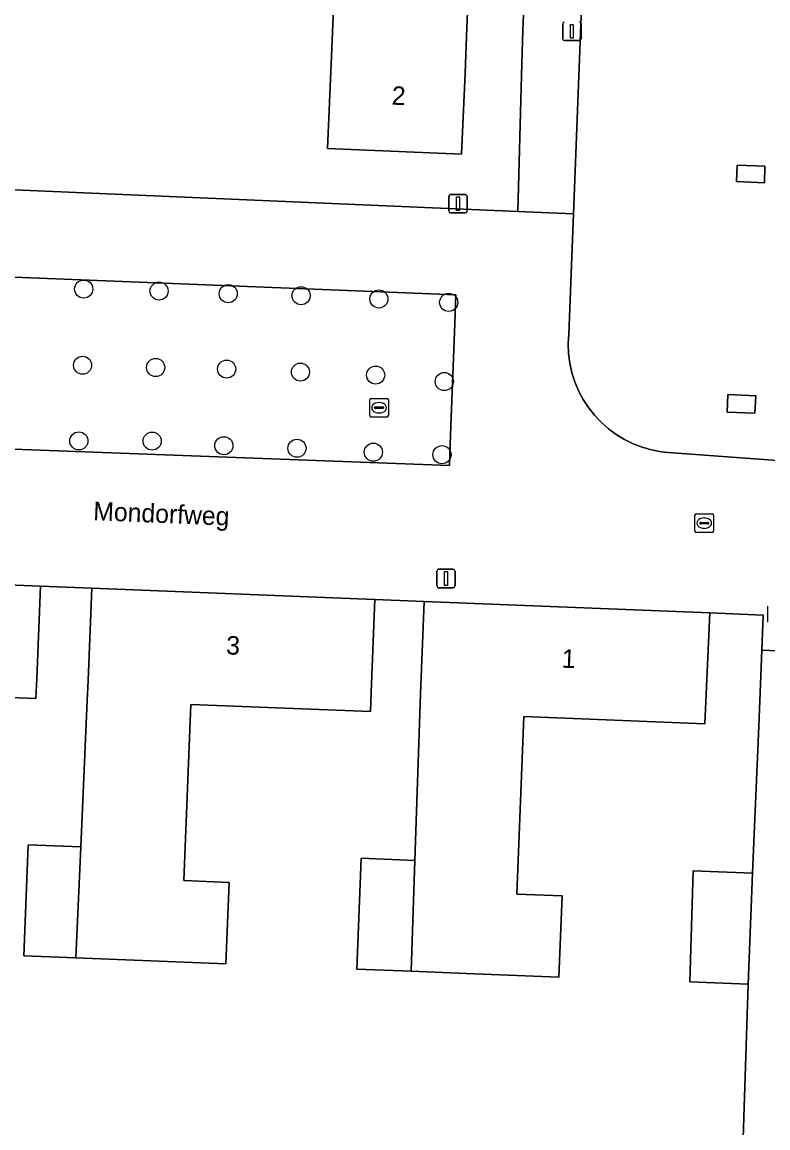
# Model space of a CAD drawing. Extents: x 160786 to 161429, y 386828 to 387485.
# Drawn here: x 160897.7 to 160938, y 387037.8 to 387097.5 of the extents above; entities that cross this region are included whole.
import ezdxf

# ---------------------------------------------------------------- set-up
doc = ezdxf.new("R2010")
doc.units = 0
for name, color, linetype in [('IMGEO_Boom', 7, 'Continuous'), ('IMGEO_Erf', 7, 'Continuous'), ('IMGEO_Kolk', 7, 'Continuous'), ('IMGEO_Lichtmast', 7, 'Continuous'), ('IMGEO_Muur', 7, 'Continuous'), ('IMGEO_Openbare_ruimte_label', 7, 'Continuous'), ('IMGEO_Pand', 7, 'Continuous'), ('IMGEO_Pand_nummerreeks', 7, 'Continuous'), ('IMGEO_Parkeervlak_open', 7, 'Continuous'), ('IMGEO_Rijbaan_lokaal_open', 7, 'Continuous'), ('IMGEO_Rioolput', 7, 'Continuous'), ('IMGEO_Voetpad_open', 7, 'Continuous')]:
    doc.layers.add(name, color=color, linetype=linetype)

msp = doc.modelspace()

# ---------------------------------------------------------------- linework, layer by layer
at = {"layer": 'IMGEO_Boom'}
for centre in [(160901.004, 387083.112), (160905.078, 387083), (160908.81, 387082.863), (160912.746, 387082.752), (160916.947, 387082.577), (160920.717, 387082.39), (160900.943, 387078.997), (160904.89, 387078.873), (160908.724, 387078.787), (160912.71, 387078.624), (160916.772, 387078.462), (160920.481, 387078.116), (160900.742, 387074.907), (160904.702, 387074.897), (160908.574, 387074.646), (160912.522, 387074.509), (160916.647, 387074.297), (160920.354, 387074.16)]:
    msp.add_circle(centre, 0.489, dxfattribs=at)
at = {"layer": 'IMGEO_Erf'}
for points in [[(160929.117, 387129.975), (160927.452, 387087.186), (160927.198, 387080.67), (160927.172, 387080.146), (160927.193, 387079.623), (160927.261, 387079.103), (160927.375, 387078.591), (160927.534, 387078.092), (160927.737, 387077.608), (160927.982, 387077.145), (160928.268, 387076.706), (160928.592, 387076.294), (160928.952, 387075.912), (160929.344, 387075.564), (160929.766, 387075.253), (160930.213, 387074.98), (160930.684, 387074.749), (160931.173, 387074.56), (160931.677, 387074.416), (160932.192, 387074.318), (160932.571, 387074.275), (160946.822, 387073.236)], [(160871.373, 387120.32), (160870.03, 387089.654), (160886.35, 387088.949), (160924.453, 387087.312), (160924.652, 387094.655), (160924.719, 387097.113), (160924.824, 387099.594)], [(160921.811, 387099.721), (160921.706, 387097.24), (160921.602, 387094.786), (160921.416, 387090.395), (160914.174, 387090.702), (160914.386, 387095.698), (160914.712, 387103.404)], [(160936.491, 387033.349), (160936.884, 387045.544), (160933.747, 387045.671), (160933.922, 387051.672), (160937.126, 387051.542), (160937.46, 387059.492), (160937.626, 387063.606), (160937.702, 387065.494), (160934.813, 387065.611), (160934.557, 387059.609), (160924.778, 387060.005), (160924.391, 387050.419), (160926.839, 387050.32), (160926.662, 387045.923), (160921.667, 387046.124), (160918.683, 387046.244), (160915.751, 387046.361), (160915.993, 387052.357), (160918.888, 387052.24), (160919.159, 387060.17), (160919.195, 387061.239), (160919.396, 387066.234), (160916.73, 387066.33), (160916.529, 387061.335), (160916.486, 387060.278), (160906.79, 387060.669), (160906.406, 387051.142), (160908.854, 387051.043), (160908.677, 387046.646), (160900.574, 387046.971), (160897.765, 387047.084), (160898.007, 387053.08), (160900.844, 387052.966), (160901.2, 387060.87), (160901.249, 387061.951), (160901.451, 387066.947), (160898.67, 387067.06), (160898.469, 387062.065), (160898.425, 387060.982), (160888.793, 387061.371)]]:
    msp.add_lwpolyline(points, dxfattribs=at)
for points in [[(160937.801, 387089.751), (160937.766, 387088.858), (160936.265, 387088.917), (160936.301, 387089.811)], [(160937.298, 387077.346), (160937.261, 387076.404), (160935.749, 387076.464), (160935.786, 387077.405)]]:
    msp.add_lwpolyline(points, close=True, dxfattribs=at)
at = {"layer": 'IMGEO_Kolk'}
for p, q in [((160916.458, 387076.271), (160916.458, 387077.123)), ((160916.533, 387077.197), (160917.385, 387077.197)), ((160916.76, 387076.74), (160917.158, 387076.74)), ((160916.946, 387076.977), (160916.971, 387076.977)), ((160917.459, 387077.123), (160917.459, 387076.271)), ((160917.385, 387076.197), (160916.533, 387076.197)), ((160916.717, 387076.691), (160916.717, 387076.703)), ((160917.155, 387076.654), (160916.757, 387076.654)), ((160916.969, 387076.417), (160916.944, 387076.417)), ((160917.201, 387076.703), (160917.201, 387076.691)), ((160934.017, 387070.035), (160934.017, 387070.887)), ((160934.092, 387070.961), (160934.944, 387070.961)), ((160935.018, 387070.887), (160935.018, 387070.035)), ((160934.276, 387070.455), (160934.276, 387070.467)), ((160934.714, 387070.418), (160934.316, 387070.418)), ((160934.319, 387070.504), (160934.717, 387070.504)), ((160934.528, 387070.181), (160934.503, 387070.181)), ((160934.505, 387070.741), (160934.53, 387070.741)), ((160934.76, 387070.467), (160934.76, 387070.455)), ((160934.944, 387069.961), (160934.092, 387069.961))]:
    msp.add_line(p, q, dxfattribs=at)
for points in [[(160916.458, 387076.271), (160916.458, 387077.123)], [(160916.533, 387077.197), (160917.385, 387077.197)], [(160917.459, 387077.123), (160917.459, 387076.271)], [(160917.385, 387076.197), (160916.533, 387076.197)], [(160934.017, 387070.035), (160934.017, 387070.887)], [(160934.092, 387070.961), (160934.944, 387070.961)], [(160935.018, 387070.887), (160935.018, 387070.035)], [(160934.944, 387069.961), (160934.092, 387069.961)]]:
    msp.add_lwpolyline(points, dxfattribs=at)
for centre, radius, start, end in [((160916.535, 387077.121), 0.0765, 91.55205, 178.44795), ((160916.535, 387077.121), 0.0765, 91.55205, 178.44795), ((160916.757, 387076.7), 0.0403, 85.87752, 175.75265), ((160917.162, 387076.702), 0.0386, 1.73085, 96.63898), ((160917.383, 387077.121), 0.0765, 1.55205, 88.44795), ((160917.383, 387077.121), 0.0765, 1.55205, 88.44795), ((160916.535, 387076.273), 0.0765, 181.55205, 268.44795), ((160916.535, 387076.273), 0.0765, 181.55205, 268.44795), ((160916.754, 387076.69), 0.0366, 178.93798, 274.71019), ((160917.158, 387076.697), 0.043, 264.86636, 352.45326), ((160917.383, 387076.273), 0.0765, 271.55205, 358.44795), ((160917.383, 387076.273), 0.0765, 271.55205, 358.44795), ((160934.094, 387070.885), 0.0765, 91.55205, 178.44795), ((160934.094, 387070.885), 0.0765, 91.55205, 178.44795), ((160934.942, 387070.885), 0.0765, 1.55205, 88.44795), ((160934.942, 387070.885), 0.0765, 1.55205, 88.44795), ((160934.316, 387070.464), 0.0403, 85.87752, 175.75265), ((160934.313, 387070.454), 0.0366, 178.93798, 274.71019), ((160934.717, 387070.461), 0.043, 264.86636, 352.45326), ((160934.721, 387070.466), 0.0386, 1.73085, 96.63898), ((160934.094, 387070.037), 0.0765, 181.55205, 268.44795), ((160934.094, 387070.037), 0.0765, 181.55205, 268.44795), ((160934.942, 387070.037), 0.0765, 271.55205, 358.44795), ((160934.942, 387070.037), 0.0765, 271.55205, 358.44795)]:
    msp.add_arc(centre, radius, start, end, dxfattribs=at)
for centre, major_axis, ratio, start_param, end_param in [((160916.945, 387076.697), (-0.387, 0.002), 0.722429, 4.712389, 7.853982), ((160916.97, 387076.697), (-0.39, 0.002), 0.717154, 1.570796, 4.712389), ((160934.504, 387070.461), (-0.387, 0.002), 0.722429, 4.712389, 7.853982), ((160934.529, 387070.461), (-0.39, 0.002), 0.717154, 1.570796, 4.712389)]:
    msp.add_ellipse(centre, major_axis=major_axis, ratio=ratio, start_param=start_param, end_param=end_param, dxfattribs=at)
at = {"layer": 'IMGEO_Lichtmast'}
for p, q in [((160926.874, 387096.638), (160926.874, 387097.438)), ((160926.874, 387097.438), (160926.874, 387096.638)), ((160927.864, 387097.438), (160927.864, 387096.638)), ((160927.864, 387096.638), (160927.864, 387097.438)), ((160927.764, 387096.538), (160926.974, 387096.538)), ((160926.974, 387096.538), (160927.764, 387096.538)), ((160920.723, 387087.324), (160920.723, 387088.124)), ((160920.723, 387088.124), (160920.723, 387087.324)), ((160920.823, 387088.224), (160921.613, 387088.224)), ((160921.613, 387088.224), (160920.823, 387088.224)), ((160921.713, 387088.124), (160921.713, 387087.324)), ((160921.713, 387087.324), (160921.713, 387088.124)), ((160921.613, 387087.224), (160920.823, 387087.224)), ((160920.823, 387087.224), (160921.613, 387087.224)), ((160920.075, 387067.067), (160920.075, 387067.867)), ((160920.075, 387067.867), (160920.075, 387067.067)), ((160920.175, 387067.967), (160920.965, 387067.967)), ((160920.965, 387067.967), (160920.175, 387067.967)), ((160921.065, 387067.867), (160921.065, 387067.067)), ((160921.065, 387067.067), (160921.065, 387067.867)), ((160920.965, 387066.967), (160920.175, 387066.967)), ((160920.175, 387066.967), (160920.965, 387066.967))]:
    msp.add_line(p, q, dxfattribs=at)
for points in [[(160927.294, 387097.413), (160927.444, 387097.413), (160927.444, 387096.663), (160927.294, 387096.663), (160927.294, 387097.413)], [(160921.143, 387088.099), (160921.293, 387088.099), (160921.293, 387087.349), (160921.143, 387087.349), (160921.143, 387088.099)], [(160920.495, 387067.842), (160920.645, 387067.842), (160920.645, 387067.092), (160920.495, 387067.092), (160920.495, 387067.842)]]:
    msp.add_lwpolyline(points, dxfattribs=at)
for centre, start, end in [((160926.974, 387097.438), 90, 180), ((160926.974, 387097.438), 90, 180), ((160927.764, 387097.438), 0, 90), ((160927.764, 387097.438), 360, 90), ((160926.974, 387096.638), 180, 270), ((160926.974, 387096.638), 180, 270), ((160927.764, 387096.638), 270, 0), ((160927.764, 387096.638), 270, 0), ((160920.823, 387088.124), 90, 180), ((160920.823, 387088.124), 90, 180), ((160921.613, 387088.124), 0, 90), ((160921.613, 387088.124), 360, 90), ((160920.823, 387087.324), 180, 270), ((160920.823, 387087.324), 180, 270), ((160921.613, 387087.324), 270, 0), ((160921.613, 387087.324), 270, 0), ((160920.175, 387067.867), 90, 180), ((160920.175, 387067.867), 90, 180), ((160920.965, 387067.867), 0, 90), ((160920.965, 387067.867), 360, 90), ((160920.175, 387067.067), 180, 270), ((160920.175, 387067.067), 180, 270), ((160920.965, 387067.067), 270, 0), ((160920.965, 387067.067), 270, 0)]:
    msp.add_arc(centre, 0.1, start, end, dxfattribs=at)
at = {"layer": 'IMGEO_Muur'}
msp.add_lwpolyline([(160937.46, 387059.492), (160937.126, 387051.542)], dxfattribs=at)
at = {"layer": 'IMGEO_Pand'}
for points in [[(160925.093, 387105.962), (160925.236, 387109.559), (160918.288, 387109.859), (160918.004, 387103.265), (160914.712, 387103.404), (160914.386, 387095.698), (160914.174, 387090.702), (160921.416, 387090.395), (160921.602, 387094.786), (160921.706, 387097.24), (160921.811, 387099.721), (160924.824, 387099.594)], [(160936.265, 387088.917), (160937.766, 387088.858), (160937.801, 387089.751), (160936.301, 387089.811)], [(160935.749, 387076.464), (160937.261, 387076.404), (160937.298, 387077.346), (160935.786, 387077.405)], [(160883.543, 387067.671), (160882.733, 387047.607), (160882.852, 387047.603), (160887.731, 387047.457), (160890.681, 387047.369), (160890.858, 387051.766), (160888.41, 387051.865), (160888.793, 387061.371), (160898.425, 387060.982), (160898.469, 387062.065), (160898.67, 387067.06), (160885.404, 387067.596)], [(160906.79, 387060.669), (160916.486, 387060.278), (160916.529, 387061.335), (160916.73, 387066.33), (160901.451, 387066.947), (160901.249, 387061.951), (160901.2, 387060.87), (160900.844, 387052.966), (160900.574, 387046.971), (160908.677, 387046.646), (160908.854, 387051.043), (160906.406, 387051.142)], [(160924.778, 387060.005), (160934.557, 387059.609), (160934.813, 387065.611), (160919.396, 387066.234), (160919.195, 387061.239), (160919.159, 387060.17), (160918.888, 387052.24), (160918.683, 387046.244), (160921.667, 387046.124), (160926.662, 387045.923), (160926.839, 387050.32), (160924.391, 387050.419)], [(160900.844, 387052.966), (160898.007, 387053.08), (160897.765, 387047.084), (160900.574, 387046.971)], [(160918.888, 387052.24), (160915.993, 387052.357), (160915.751, 387046.361), (160918.683, 387046.244)], [(160937.126, 387051.542), (160933.922, 387051.672), (160933.747, 387045.671), (160936.884, 387045.544)]]:
    msp.add_lwpolyline(points, close=True, dxfattribs=at)
at = {"layer": 'IMGEO_Parkeervlak_open'}
msp.add_lwpolyline([(160921.048, 387081.254), (160921.106, 387082.794), (160892.287, 387083.947), (160892.225, 387082.407), (160891.99, 387076.457), (160891.919, 387074.654), (160920.761, 387073.576), (160920.823, 387075.234)], close=True, dxfattribs=at)
at = {"layer": 'IMGEO_Rijbaan_lokaal_open'}
for points in [[(160946.822, 387073.236), (160932.571, 387074.275), (160932.192, 387074.318), (160931.677, 387074.416), (160931.173, 387074.56), (160930.684, 387074.749), (160930.213, 387074.98), (160929.766, 387075.253), (160929.344, 387075.564), (160928.952, 387075.912), (160928.592, 387076.294), (160928.268, 387076.706), (160927.982, 387077.145), (160927.737, 387077.608), (160927.534, 387078.092), (160927.375, 387078.591), (160927.261, 387079.103), (160927.193, 387079.623), (160927.172, 387080.146), (160927.198, 387080.67), (160927.452, 387087.186), (160924.453, 387087.312), (160886.35, 387088.949)], [(160885.404, 387067.596), (160898.67, 387067.06), (160901.451, 387066.947), (160916.73, 387066.33), (160919.396, 387066.234), (160934.813, 387065.611), (160937.702, 387065.494), (160937.626, 387063.606), (160940.588, 387063.47), (160943.59, 387063.347), (160946.593, 387063.224), (160949.595, 387063.101), (160952.598, 387062.978), (160955.6, 387062.855), (160958.603, 387062.732), (160961.605, 387062.609), (160964.608, 387062.486), (160967.61, 387062.363), (160970.17, 387062.263), (160970.32, 387065.784), (160984.552, 387065.241)]]:
    msp.add_lwpolyline(points, dxfattribs=at)
msp.add_lwpolyline([(160920.823, 387075.234), (160920.761, 387073.576), (160891.919, 387074.654), (160891.99, 387076.457), (160892.225, 387082.407), (160892.287, 387083.947), (160921.106, 387082.794), (160921.048, 387081.254)], close=True, dxfattribs=at)
at = {"layer": 'IMGEO_Rioolput'}
msp.add_line((160937.956, 387065.119), (160937.956, 387065.971), dxfattribs=at)
msp.add_lwpolyline([(160937.956, 387065.119), (160937.956, 387065.971)], dxfattribs=at)
at = {"layer": 'IMGEO_Voetpad_open'}
for points in [[(160929.117, 387129.975), (160929.314, 387134.437), (160926.292, 387134.589), (160926.195, 387132.113), (160925.836, 387124.081), (160925.577, 387118.089), (160925.236, 387109.559), (160925.093, 387105.962), (160924.824, 387099.594), (160924.719, 387097.113), (160924.652, 387094.655), (160924.453, 387087.312), (160927.452, 387087.186)], [(160937.126, 387051.542), (160936.884, 387045.544), (160936.491, 387033.349), (160936.116, 387024.42), (160935.762, 387014.709), (160938.734, 387014.625), (160940.342, 387057.48), (160940.588, 387063.47), (160937.626, 387063.606), (160937.46, 387059.492)]]:
    msp.add_lwpolyline(points, close=True, dxfattribs=at)

# ---------------------------------------------------------------- texts
at = {"layer": 'IMGEO_Openbare_ruimte_label'}
msp.add_text('Mondorfweg', height=1, rotation=357.7071, dxfattribs=at).set_placement((160901.506, 387070.623))
at = {"layer": 'IMGEO_Pand_nummerreeks'}
for s, rotation, p in [('2', 357.57066, (160917.625, 387093.079)), ('3', 357.68525, (160908.683, 387063.372)), ('1', 357.68525, (160926.811, 387062.652))]:
    msp.add_text(s, height=1, rotation=rotation, dxfattribs=at).set_placement(p)

doc.saveas('drawing.dxf')
